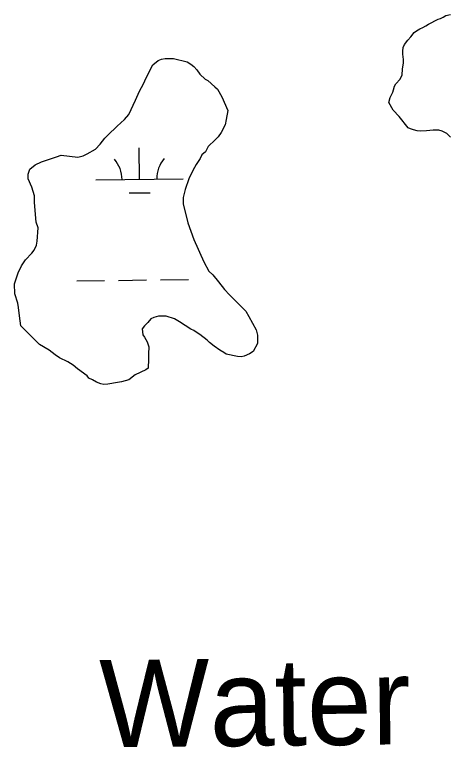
# Model space of a CAD drawing. Extents: x 3702978 to 3741108, y 397120 to 422907.
# Drawn here: x 3707730 to 3708229, y 412087 to 412926 of the extents above; entities that cross this region are included whole.
import ezdxf

# ---------------------------------------------------------------- set-up
doc = ezdxf.new("R2010")
doc.units = 0
for name, color, linetype in [('V-RIVR-IDEN', 7, 'Continuous'), ('V-TOPO-SHOR', 7, 'Continuous'), ('V-WETL-SWMP', 7, 'Continuous')]:
    doc.layers.add(name, color=color, linetype=linetype)

msp = doc.modelspace()

# ---------------------------------------------------------------- linework, layer by layer
at = {"layer": 'V-TOPO-SHOR'}
for p, q in [((3708220.964, 412923.459), (3708223.943, 412925.379)), ((3708223.943, 412925.379), (3708229.365, 412926.278)), ((3708204.125, 412915.363), (3708215.028, 412921.093)), ((3708215.028, 412921.093), (3708217.992, 412922.03)), ((3708217.992, 412922.03), (3708220.964, 412923.459)), ((3708190.242, 412907.712), (3708194.212, 412910.109)), ((3708194.212, 412910.109), (3708197.675, 412911.53)), ((3708197.675, 412911.53), (3708201.146, 412913.443)), ((3708201.146, 412913.443), (3708204.125, 412915.363)), ((3708180.245, 412897.052), (3708183.746, 412900.931)), ((3708183.746, 412900.931), (3708187.754, 412905.785)), ((3708187.754, 412905.785), (3708190.242, 412907.712)), ((3708175.201, 412888.774), (3708176.729, 412892.191)), ((3708176.729, 412892.191), (3708180.245, 412897.052)), ((3708174.588, 412880.918), (3708174.641, 412884.358)), ((3708174.641, 412884.358), (3708175.201, 412888.774)), ((3708175.48, 412875.005), (3708174.588, 412880.918)), ((3708175.419, 412871.073), (3708175.48, 412875.005)), ((3708174.322, 412863.716), (3708175.419, 412871.073)), ((3708173.731, 412857.335), (3708174.322, 412863.716)), ((3708166.691, 412847.121), (3708171.689, 412852.451)), ((3708171.689, 412852.451), (3708173.731, 412857.335)), ((3708164.127, 412840.278), (3708165.171, 412844.195)), ((3708165.171, 412844.195), (3708166.691, 412847.121)), ((3708160.058, 412831.493), (3708163.098, 412837.345)), ((3708163.098, 412837.345), (3708164.127, 412840.278)), ((3708158.493, 412825.618), (3708160.058, 412831.493)), ((3708163.762, 412816.688), (3708158.493, 412825.618)), ((3708170.536, 412809.701), (3708163.762, 412816.688)), ((3708180.659, 412796.763), (3708170.536, 412809.701)), ((3708183.584, 412795.243), (3708180.659, 412796.763)), ((3708187.01, 412794.207), (3708183.584, 412795.243)), ((3708190.926, 412793.163), (3708187.01, 412794.207)), ((3708195.342, 412792.603), (3708190.926, 412793.163)), ((3708201.738, 412792.996), (3708195.342, 412792.603)), ((3708209.617, 412793.857), (3708201.738, 412792.996)), ((3708216.006, 412793.758), (3708209.617, 412793.857)), ((3708219.922, 412792.714), (3708216.006, 412793.758)), ((3708225.29, 412790.173), (3708219.922, 412792.714)), ((3708229.154, 412785.689), (3708225.29, 412790.173))]:
    msp.add_line(p, q, dxfattribs=at)
for points in [[(3707860.332, 412811.788), (3707868.213, 412828.286), (3707872.799, 412838.59), (3707877.421, 412846.851), (3707878.722, 412850.282), (3707885.947, 412865.404), (3707887.929, 412868.847), (3707893.975, 412873.726), (3707898.038, 412875.162), (3707902.114, 412875.917), (3707911.651, 412876.088), (3707927.394, 412872.282), (3707931.53, 412869.63), (3707934.986, 412866.966), (3707938.465, 412862.94), (3707941.957, 412858.232), (3707948.199, 412852.211), (3707950.948, 412850.897), (3707959.258, 412843.55), (3707962.032, 412840.874), (3707966.96, 412832.103), (3707974.054, 412816.556), (3707972.193, 412806.301), (3707970.941, 412800.145), (3707966.331, 412791.203), (3707963.011, 412786.373), (3707959.665, 412782.905), (3707951.625, 412775.264), (3707948.328, 412769.072), (3707944.302, 412765.592), (3707942.332, 412761.468), (3707937.685, 412754.57), (3707933.72, 412747.684), (3707929.122, 412738.06), (3707925.255, 412725.724), (3707922.689, 412716.819), (3707922.823, 412709.325), (3707927.984, 412687.61), (3707935.139, 412668.657), (3707946.504, 412642.965), (3707952.15, 412632.162), (3707956.992, 412628.16), (3707963.27, 412620.095), (3707970.242, 412611.361), (3707975.802, 412605.328), (3707981.35, 412599.975), (3707994.539, 412586.582), (3707998.055, 412580.512), (3708006.511, 412564.99), (3708007.984, 412558.883), (3708008.155, 412549.345), (3708002.864, 412540.391), (3707998.826, 412537.593), (3707992.743, 412534.757), (3707989.349, 412534.015), (3707985.249, 412534.623), (3707972.256, 412537.116), (3707969.495, 412539.11), (3707964.677, 412541.75), (3707958.46, 412546.409), (3707952.936, 412550.398), (3707950.162, 412553.074), (3707941.865, 412559.74), (3707937.728, 412562.392), (3707934.966, 412564.387), (3707931.536, 412565.688), (3707918.433, 412574.312), (3707912.921, 412577.621), (3707903.323, 412580.856), (3707894.466, 412580.697), (3707889.04, 412579.236), (3707885.659, 412577.813), (3707882.326, 412573.664), (3707878.311, 412569.503), (3707875.648, 412566.048), (3707876.451, 412559.247), (3707878.544, 412556.559), (3707881.367, 412551.158), (3707883.508, 412545.744), (3707882.974, 412537.557), (3707883.084, 412531.426), (3707882.586, 412521.194), (3707879.898, 412519.102), (3707867.733, 412513.431), (3707860.337, 412507.847), (3707852.198, 412505.656), (3707847.442, 412504.889), (3707836.578, 412502.65), (3707831.809, 412502.564), (3707828.391, 412503.184), (3707823.585, 412505.142), (3707818.768, 412507.782), (3707814.643, 412509.752), (3707812.551, 412512.441), (3707801.504, 412520.42), (3707796.661, 412524.422), (3707790.457, 412528.399), (3707780.833, 412532.997), (3707776.003, 412536.318), (3707769.093, 412541.646), (3707758.07, 412548.263)], [(3707758.07, 412548.263), (3707736.56, 412569.684), (3707734.989, 412581.241), (3707734.137, 412590.766), (3707733.37, 412595.523), (3707729.768, 412606.362), (3707729.56, 412617.943), (3707733.427, 412630.28), (3707737.368, 412638.528), (3707742.014, 412645.426), (3707749.374, 412653.055), (3707752.038, 412656.51), (3707754.665, 412662.009), (3707755.261, 412666.79), (3707756.354, 412681.803), (3707754.188, 412688.578), (3707752.422, 412711.036), (3707752.287, 412718.53), (3707749.379, 412728.7), (3707745.12, 412738.164), (3707745.022, 412743.614), (3707746.968, 412749.101), (3707753.014, 412753.98), (3707760.446, 412757.521), (3707777.38, 412763.277), (3707782.793, 412765.418), (3707801.918, 412763.036), (3707808.025, 412764.508), (3707812.757, 412766.638), (3707822.197, 412772.259), (3707827.549, 412777.807), (3707832.877, 412784.718), (3707836.222, 412788.185), (3707846.939, 412798.6), (3707855.661, 412806.253), (3707860.332, 412811.788)]]:
    msp.add_lwpolyline(points, dxfattribs=at)
at = {"layer": 'V-WETL-SWMP'}
for p, q in [((3708220.964, 412923.459), (3708223.943, 412925.379)), ((3708223.943, 412925.379), (3708229.365, 412926.278)), ((3708204.125, 412915.363), (3708215.028, 412921.093)), ((3708215.028, 412921.093), (3708217.992, 412922.03)), ((3708217.992, 412922.03), (3708220.964, 412923.459)), ((3708190.242, 412907.712), (3708194.212, 412910.109)), ((3708194.212, 412910.109), (3708197.675, 412911.53)), ((3708197.675, 412911.53), (3708201.146, 412913.443)), ((3708201.146, 412913.443), (3708204.125, 412915.363)), ((3708180.245, 412897.052), (3708183.746, 412900.931)), ((3708183.746, 412900.931), (3708187.754, 412905.785)), ((3708187.754, 412905.785), (3708190.242, 412907.712)), ((3708175.201, 412888.774), (3708176.729, 412892.191)), ((3708176.729, 412892.191), (3708180.245, 412897.052)), ((3708174.588, 412880.918), (3708174.641, 412884.358)), ((3708174.641, 412884.358), (3708175.201, 412888.774)), ((3708175.48, 412875.005), (3708174.588, 412880.918)), ((3708175.419, 412871.073), (3708175.48, 412875.005)), ((3708174.322, 412863.716), (3708175.419, 412871.073)), ((3708173.731, 412857.335), (3708174.322, 412863.716)), ((3708166.691, 412847.121), (3708171.689, 412852.451)), ((3708171.689, 412852.451), (3708173.731, 412857.335)), ((3708164.127, 412840.278), (3708165.171, 412844.195)), ((3708165.171, 412844.195), (3708166.691, 412847.121)), ((3708160.058, 412831.493), (3708163.098, 412837.345)), ((3708163.098, 412837.345), (3708164.127, 412840.278)), ((3708158.493, 412825.618), (3708160.058, 412831.493)), ((3708163.762, 412816.688), (3708158.493, 412825.618)), ((3708170.536, 412809.701), (3708163.762, 412816.688)), ((3708180.659, 412796.763), (3708170.536, 412809.701)), ((3708183.584, 412795.243), (3708180.659, 412796.763)), ((3708187.01, 412794.207), (3708183.584, 412795.243)), ((3708190.926, 412793.163), (3708187.01, 412794.207)), ((3708195.342, 412792.603), (3708190.926, 412793.163)), ((3708201.738, 412792.996), (3708195.342, 412792.603)), ((3708209.617, 412793.857), (3708201.738, 412792.996)), ((3708216.006, 412793.758), (3708209.617, 412793.857)), ((3708219.922, 412792.714), (3708216.006, 412793.758)), ((3708225.29, 412790.173), (3708219.922, 412792.714)), ((3708229.154, 412785.689), (3708225.29, 412790.173)), ((3707872.716, 412737.533), (3707872.269, 412773.53)), ((3707822.72, 412736.911), (3707922.712, 412738.154)), ((3707860.909, 412721.954), (3707884.907, 412722.252)), ((3707800.747, 412621.198), (3707832.745, 412621.595)), ((3707848.744, 412621.794), (3707880.741, 412622.191)), ((3707896.74, 412622.39), (3707928.738, 412622.788))]:
    msp.add_line(p, q, dxfattribs=at)
for points in [[(3707860.332, 412811.788), (3707868.213, 412828.286), (3707872.799, 412838.59), (3707877.421, 412846.851), (3707878.722, 412850.282), (3707885.947, 412865.404), (3707887.929, 412868.847), (3707893.975, 412873.726), (3707898.038, 412875.162), (3707902.114, 412875.917), (3707911.651, 412876.088), (3707927.394, 412872.282), (3707931.53, 412869.63), (3707934.986, 412866.966), (3707938.465, 412862.94), (3707941.957, 412858.232), (3707948.199, 412852.211), (3707950.948, 412850.897), (3707959.258, 412843.55), (3707962.032, 412840.874), (3707966.96, 412832.103), (3707974.054, 412816.556), (3707972.193, 412806.301), (3707970.941, 412800.145), (3707966.331, 412791.203), (3707963.011, 412786.373), (3707959.665, 412782.905), (3707951.625, 412775.264), (3707948.328, 412769.072), (3707944.302, 412765.592), (3707942.332, 412761.468), (3707937.685, 412754.57), (3707933.72, 412747.684), (3707929.122, 412738.06), (3707925.255, 412725.724), (3707922.689, 412716.819), (3707922.823, 412709.325), (3707927.984, 412687.61), (3707935.139, 412668.657), (3707946.504, 412642.965), (3707952.15, 412632.162), (3707956.992, 412628.16), (3707963.27, 412620.095), (3707970.242, 412611.361), (3707975.802, 412605.328), (3707981.35, 412599.975), (3707994.539, 412586.582), (3707998.055, 412580.512), (3708006.511, 412564.99), (3708007.984, 412558.883), (3708008.155, 412549.345), (3708002.864, 412540.391), (3707998.826, 412537.593), (3707992.743, 412534.757), (3707989.349, 412534.015), (3707985.249, 412534.623), (3707972.256, 412537.116), (3707969.495, 412539.11), (3707964.677, 412541.75), (3707958.46, 412546.409), (3707952.936, 412550.398), (3707950.162, 412553.074), (3707941.865, 412559.74), (3707937.728, 412562.392), (3707934.966, 412564.387), (3707931.536, 412565.688), (3707918.433, 412574.312), (3707912.921, 412577.621), (3707903.323, 412580.856), (3707894.466, 412580.697), (3707889.04, 412579.236), (3707885.659, 412577.813), (3707882.326, 412573.664), (3707878.311, 412569.503), (3707875.648, 412566.048), (3707876.451, 412559.247), (3707878.544, 412556.559), (3707881.367, 412551.158), (3707883.508, 412545.744), (3707882.974, 412537.557), (3707883.084, 412531.426), (3707882.586, 412521.194), (3707879.898, 412519.102), (3707867.733, 412513.431), (3707860.337, 412507.847), (3707852.198, 412505.656), (3707847.442, 412504.889), (3707836.578, 412502.65), (3707831.809, 412502.564), (3707828.391, 412503.184), (3707823.585, 412505.142), (3707818.768, 412507.782), (3707814.643, 412509.752), (3707812.551, 412512.441), (3707801.504, 412520.42), (3707796.661, 412524.422), (3707790.457, 412528.399), (3707780.833, 412532.997), (3707776.003, 412536.318), (3707769.093, 412541.646), (3707758.07, 412548.263)], [(3707758.07, 412548.263), (3707736.56, 412569.684), (3707734.989, 412581.241), (3707734.137, 412590.766), (3707733.37, 412595.523), (3707729.768, 412606.362), (3707729.56, 412617.943), (3707733.427, 412630.28), (3707737.368, 412638.528), (3707742.014, 412645.426), (3707749.374, 412653.055), (3707752.038, 412656.51), (3707754.665, 412662.009), (3707755.261, 412666.79), (3707756.354, 412681.803), (3707754.188, 412688.578), (3707752.422, 412711.036), (3707752.287, 412718.53), (3707749.379, 412728.7), (3707745.12, 412738.164), (3707745.022, 412743.614), (3707746.968, 412749.101), (3707753.014, 412753.98), (3707760.446, 412757.521), (3707777.38, 412763.277), (3707782.793, 412765.418), (3707801.918, 412763.036), (3707808.025, 412764.508), (3707812.757, 412766.638), (3707822.197, 412772.259), (3707827.549, 412777.807), (3707832.877, 412784.718), (3707836.222, 412788.185), (3707846.939, 412798.6), (3707855.661, 412806.253), (3707860.332, 412811.788)]]:
    msp.add_lwpolyline(points, dxfattribs=at)
for centre, start, end in [((3707817.471, 412737.321), 359.939883, 41.483542), ((3707927.949, 412738.693), 139.93988, 181.483539)]:
    msp.add_arc(centre, 35.246, start, end, dxfattribs=at)

# ---------------------------------------------------------------- texts
at = {"layer": 'V-RIVR-IDEN'}
msp.add_text('Water', height=99.9998, rotation=0.572928, dxfattribs=at).set_placement((3707827.295, 412086.599))

doc.saveas('drawing.dxf')
